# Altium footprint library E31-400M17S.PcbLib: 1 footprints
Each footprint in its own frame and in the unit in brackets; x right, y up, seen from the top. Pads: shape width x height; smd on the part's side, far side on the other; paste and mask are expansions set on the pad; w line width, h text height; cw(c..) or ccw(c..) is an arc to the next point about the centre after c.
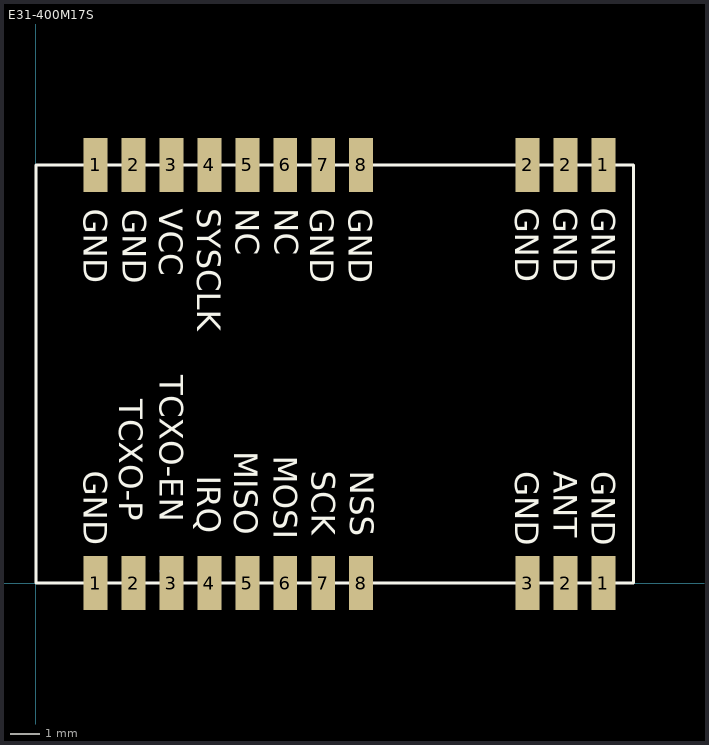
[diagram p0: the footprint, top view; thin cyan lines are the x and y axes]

## E31-400M17S [mm] "U*"
pads (22):
  rect 0.8x1.8 smd: 1(2,0) 1(2,14) 1(19,0) 1(19,14) 2(3.27,0) 2(3.27,14) 2(16.46,14) 2(17.73,0) 2(17.73,14) 3(4.54,0) 3(4.54,14) 3(16.46,0) 4(5.81,0) 4(5.81,14) 5(7.08,0) 5(7.08,14) 6(8.35,0) 6(8.35,14) 7(9.62,0) 7(9.62,14) 8(10.89,0) 8(10.89,14)
Top Layer:
  region: 3.27,14
Bottom Layer:
  region: 21.3,0
  lines w0.21: 4.245,0.395 4.275,0.365 4.54,0.365 4.54,0
Top Overlay:
  lines w0.1: 0,0 0,14 20,14 20,0 0,0
  text "SYSCLK" at 5.4,12.55 h0.8
  text "GND" at 1.6,3.76 h0.8
  text "TCXO-P" at 2.8,6.15 h0.8
  text "TCXO-EN" at 4.15,6.95 h0.8
  text "IRQ" at 5.4,3.6 h0.8
  text "MISO" at 6.636,4.41 h0.8
  text "MOSI" at 7.964,4.26 h0.8
  text "SCK" at 9.243,3.76 h0.8
  text "NSS" at 10.522,3.76 h0.8
  text "GND" at 16.054,3.74 h0.8
  text "ANT" at 17.333,3.74 h0.8
  text "GND" at 18.612,3.74 h0.8
  text "GND" at 18.612,12.56 h0.8
  text "GND" at 17.333,12.56 h0.8
  text "GND" at 16.054,12.56 h0.8
  text "GND" at 10.472,12.53 h0.8
  text "GND" at 9.193,12.53 h0.8
  text "NC" at 8,12.55 h0.8
  text "NC" at 6.7,12.55 h0.8
  text "VCC" at 4.128,12.53 h0.8
  text "GND" at 2.91,12.51 h0.8
  text "GND" at 1.6,12.53 h0.8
